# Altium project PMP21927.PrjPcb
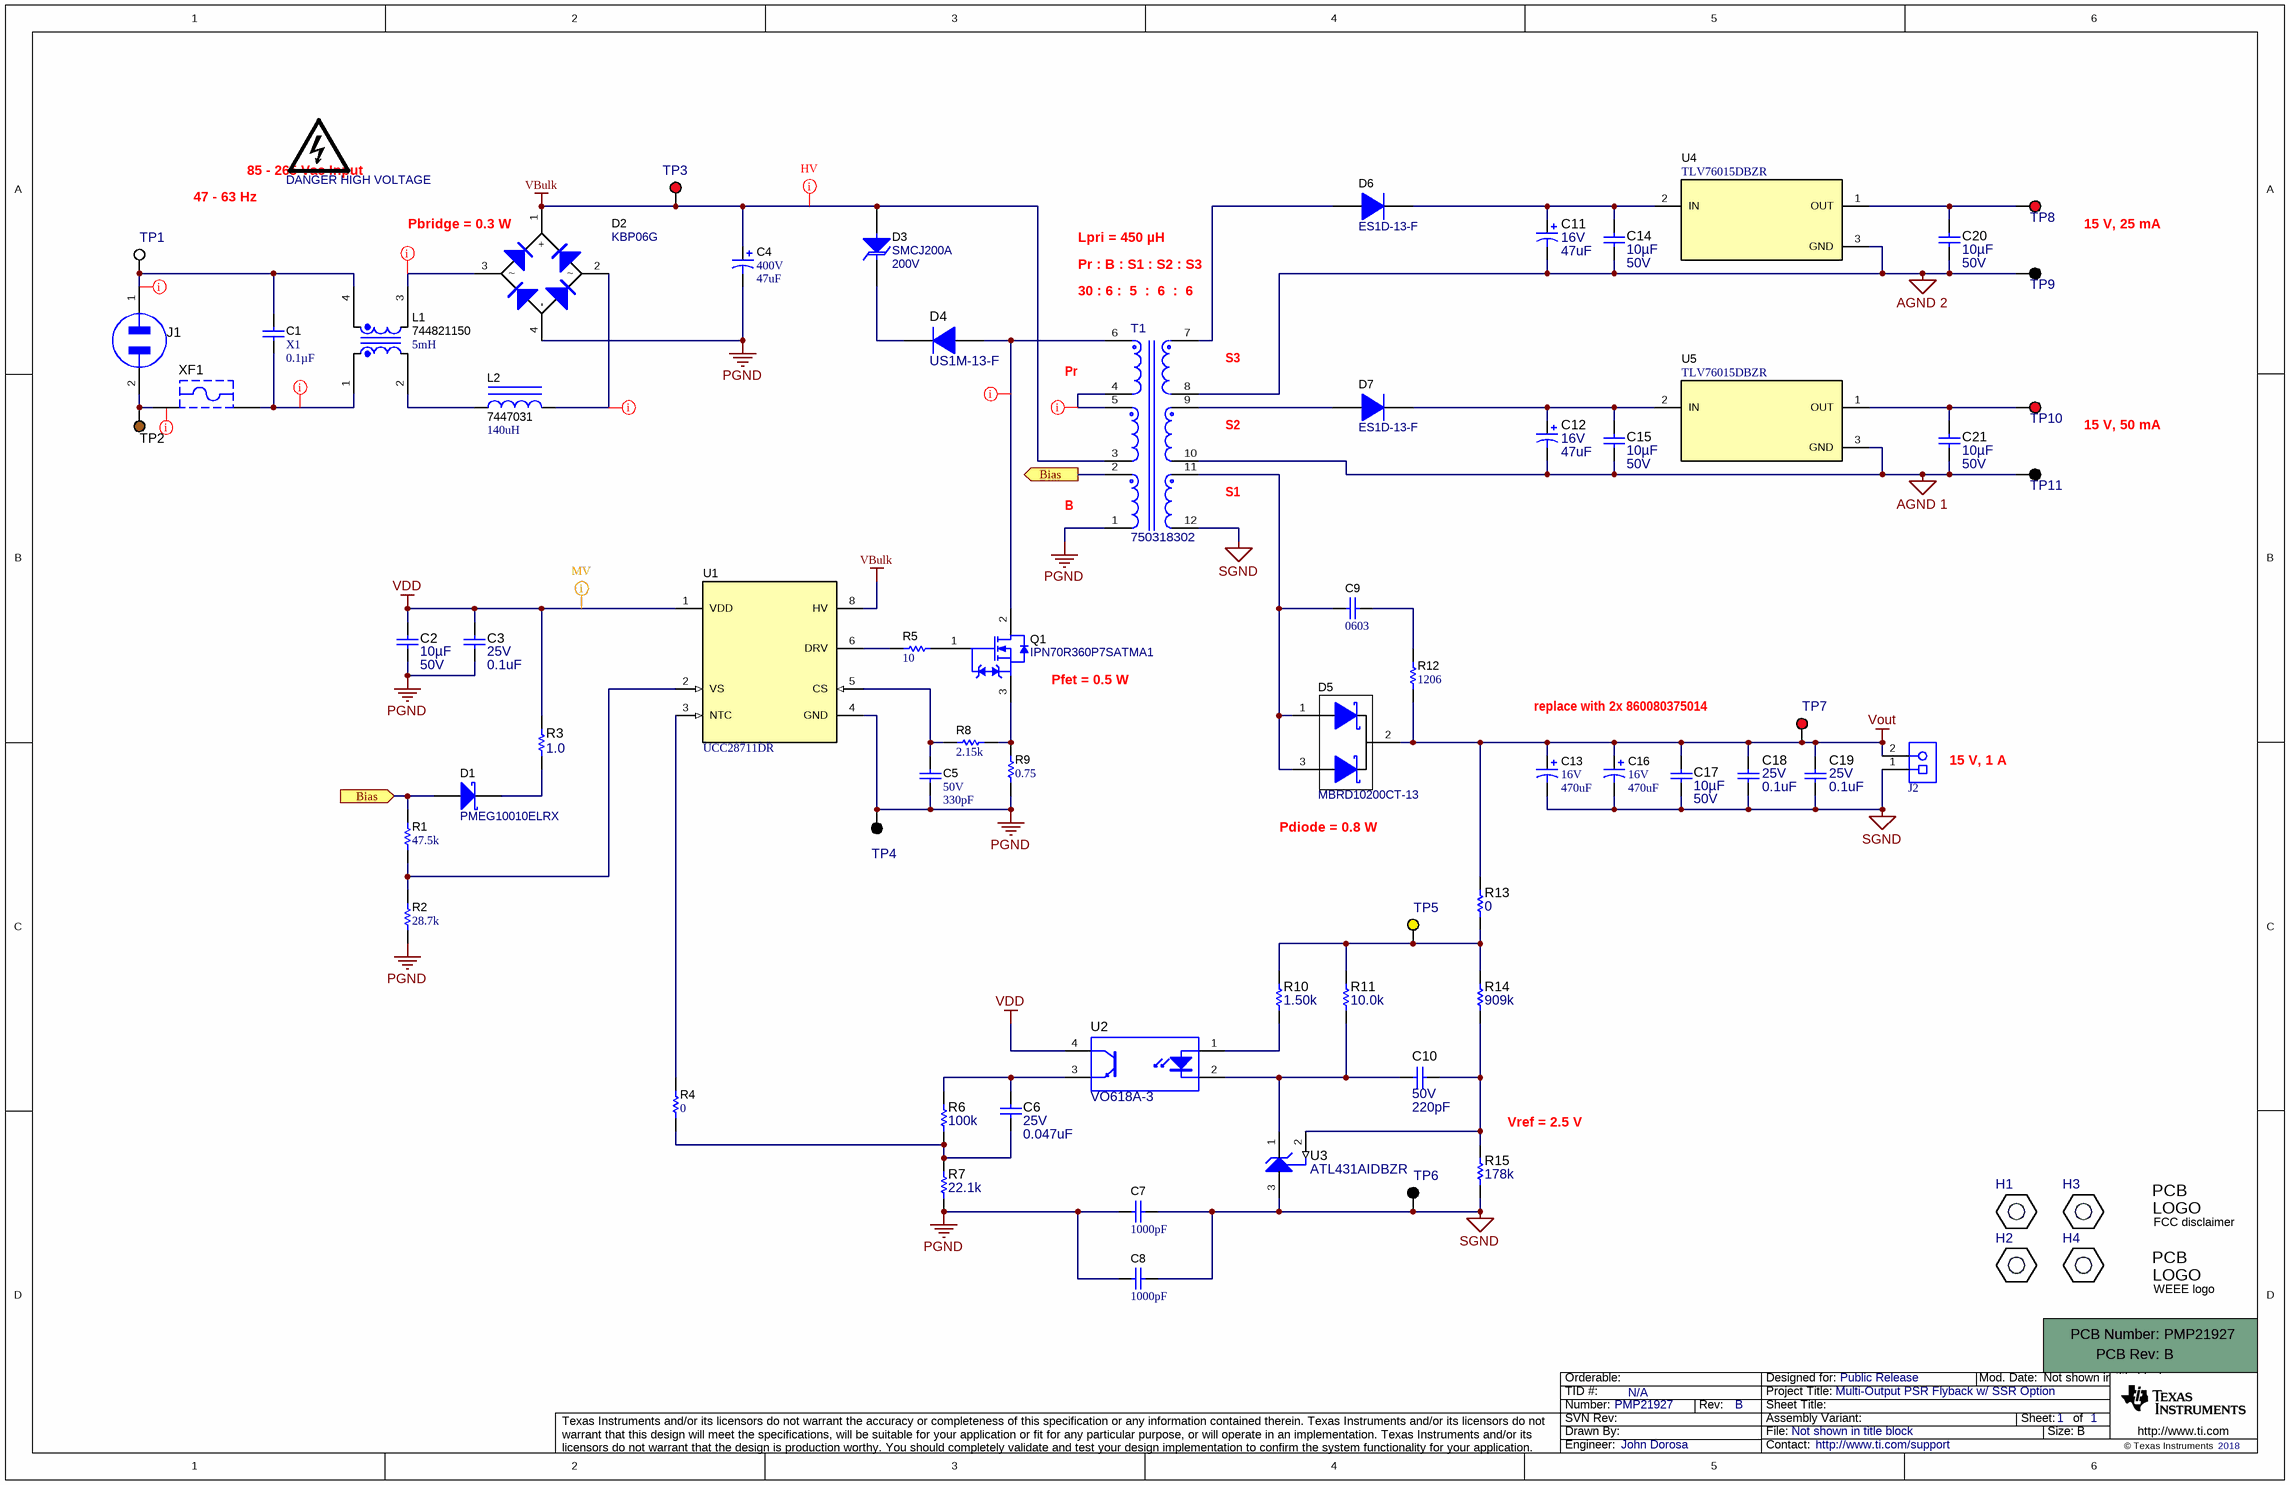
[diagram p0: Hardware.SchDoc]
CopyrightYear: 2018; PCB_Layout: John Dorosa; PCB_Rev: B; PRJ_Customer: Public Release; PRJ_Engineer: John Dorosa; PRJ_Number: PMP21927; PRJ_Title: Multi-Output PSR Flyback w/ SSR Option; SCH_Rev: B; TechSupport: http://www.ti.com/support; TID: N/A
1 sheet, 74 parts. Net scope: flat (ports and power ports of the same name join across sheets).
Board file: PCB.PcbDoc

## Sheet Hardware.SchDoc
size 431 x 279 mm; Date: Not shown in title block; ApprovedBy: Not shown in title block; CheckedBy: Not shown in title block; Author: Not shown in title block; CompanyName: Not shown in title block; Engineer: Not shown in title block; Organization: Not shown in title block; Address1: Not shown in title block; Address2: Not shown in title block; Address3: Not shown in title block; Address4: Not shown in title block; DocumentNumber: 1; Revision: Use project parameter SCH_Rev; SheetNumber: 1; SheetTotal: 1; PageSetup: Record=PageOptions¦CenterHorizontal=True¦CenterVertical=True¦PrintScale=1.00¦XCorrection=1.00¦YCorrection=1.00¦PrintKind=0¦BorderSize=5000000¦LeftOffset=0¦BottomOffset=0¦Orientation=2¦PaperLength=1000¦PaperWidth=1000¦Scale=100¦PaperSource=15¦PrintQuality=600¦MediaType=1¦DitherType=10¦PaperKind=Letter¦PrintScaleMode=1

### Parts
!PCB1  Printed Circuit Board  (value not drawn)  (mechanical)
C1  AC_Safety: X1  ValueDisplayed: 0.1µF  [Kemet_1800x1100x1900]  (hidden comment: R474I310050A1K)
C2  ValueDisplayed: 10µF  VDC_V: 50V  [1206_190]  (hidden comment: CGA5L1X7R1H106K160AC)
C3  VDC_V: 25V  ValueDisplayed: 0.1uF  [0603]  (hidden comment: C1608X7R1E104K080AA)
C4  VDC_V: 400V  ValueDisplayed: 47uF  [CAPPR7_5-16X25_HorizontalDown]  (hidden comment: UCS2G470MHD)
C5  VDC_V: 50V  ValueDisplayed: 330pF  [0402]  (hidden comment: GRM155R71H331KA01D)
C6  VDC_V: 25V  ValueDisplayed: 0.047uF  [0603]  (hidden comment: GRM188R71E473KA01D)
C7  ValueDisplayed: 1000pF  [VY1_900x500x1300]  (hidden comment: VY1102M35Y5UQ63V0)
C8  ValueDisplayed: 1000pF  [VY1_900x500x1300]  (hidden comment: VY1102M35Y5UQ63V0)
C9  GRM188R72A102KA01D  [0603]  (value not drawn)
C10  VDC_V: 50V  ValueDisplayed: 220pF  [0603]  (hidden comment: GRM188R71H221KA01D)
C11  VDC_V: 16V  ValueDisplayed: 47uF  [FC_500x1100]  (hidden comment: EEUFC1C470)
C12  VDC_V: 16V  ValueDisplayed: 47uF  [FC_500x1100]  (hidden comment: EEUFC1C470)
C13  VDC_V: 16V  ValueDisplayed: 470uF  [Chemi-Con_1000x1250]  (hidden comment: EKZE160ELL471MJC5S)
C14  ValueDisplayed: 10µF  VDC_V: 50V  [1206_190]  (hidden comment: CGA5L1X7R1H106K160AC)
C15  ValueDisplayed: 10µF  VDC_V: 50V  [1206_190]  (hidden comment: CGA5L1X7R1H106K160AC)
C16  VDC_V: 16V  ValueDisplayed: 470uF  [Chemi-Con_1000x1250]  (hidden comment: EKZE160ELL471MJC5S)
C17  ValueDisplayed: 10µF  VDC_V: 50V  [1206_190]  (hidden comment: CGA5L1X7R1H106K160AC)
C18  VDC_V: 25V  ValueDisplayed: 0.1uF  [0603]  (hidden comment: C1608X7R1E104K080AA)
C19  VDC_V: 25V  ValueDisplayed: 0.1uF  [0603]  (hidden comment: C1608X7R1E104K080AA)
C20  ValueDisplayed: 10µF  VDC_V: 50V  [1206_190]  (hidden comment: CGA5L1X7R1H106K160AC)
C21  ValueDisplayed: 10µF  VDC_V: 50V  [1206_190]  (hidden comment: CGA5L1X7R1H106K160AC)
D1  PMEG10010ELRX  [SOD-123W]
D2  KBP06G  [KBP]
D3  SMCJ200A  value 200V  [SMC]
D4  US1M-13-F  [SMA]
D5  MBRD10200CT-13  [DPAK]
D6  ES1D-13-F  [SMA]
D7  ES1D-13-F  [SMA]
H1  4826  [KEYSTONE_4826]  (value not drawn)
H2  4826  [KEYSTONE_4826]  (value not drawn)
H3  4826  [KEYSTONE_4826]  (value not drawn)
H4  4826  [KEYSTONE_4826]  (value not drawn)
J1  770W-X2/10  [CONN_AC_770W-SERIES]  (value not drawn)
J2  691214310002  [Wurth_691214310002]  (value not drawn)
L1  744821150  value 5mH  [WE-CMB_XS]
L2  7447031  ValueDisplayed: 140uH  [WE-FI_1350x700]
LOGO1  DANGER HIGH VOLTAGE  [IEC_HighVoltage_Medium]  (no BOM)
Logo2  FCC disclaimer  [FCC_disclaimer]  (no BOM)
Logo3  WEEE logo  [WEEE_Minimum]  (no BOM)
Q1  IPN70R360P7SATMA1  [PG-SOT223]
R1  ValueDisplayed: 47.5k  [0603]  (hidden comment: CRCW060347K5FKEA)
R2  ValueDisplayed: 28.7k  [0603]  (hidden comment: CRCW060328K7FKEA)
R3  ValueDisplayed: 1.0  [0603]  (hidden comment: CRCW06031R00JNEA)
R4  ValueDisplayed: 0  [1206]  (hidden comment: CRCW12060000Z0EA)
R5  ValueDisplayed: 10  [0603]  (hidden comment: CRCW060310R0JNEA)
R6  ValueDisplayed: 100k  [0603]  (hidden comment: CRCW0603100KFKEA)
R7  ValueDisplayed: 22.1k  [0603]  (hidden comment: CRCW060322K1FKEA)
R8  ValueDisplayed: 2.15k  [0603]  (hidden comment: CRCW06032K15FKEA)
R9  ValueDisplayed: 0.75  [2010]  (hidden comment: CSRN2010FKR750)
R10  ValueDisplayed: 1.50k  [0603]  (hidden comment: CRCW06031K50FKEA)
R11  ValueDisplayed: 10.0k  [0603]  (hidden comment: CRCW060310K0FKEA)
R12  CRCW1206200RJNEA  [1206]  (value not drawn)
R13  ValueDisplayed: 0  [0603]  (hidden comment: CRCW06030000Z0EA)
R14  ValueDisplayed: 909k  [0603]  (hidden comment: CRCW0603909KFKEA)
R15  ValueDisplayed: 178k  [0603]  (hidden comment: CRCW0603178KFKEA)
T1  750318302  [FP-750318302_TRANS_PTH_33MM0_26MM3-MFG]
TP1  5012  [Keystone5012]  (value not drawn)
TP2  5125  [Keystone5125]  (value not drawn)
TP3  5010  [Keystone5010]  (value not drawn)
TP4  5011  [Keystone5011]  (value not drawn)
TP5  5014  [Keystone5014]  (value not drawn)
TP6  5011  [Keystone5011]  (value not drawn)
TP7  5010  [Keystone5010]  (value not drawn)
TP8  5010  [Keystone5010]  (value not drawn)
TP9  5011  [Keystone5011]  (value not drawn)
TP10  5010  [Keystone5010]  (value not drawn)
TP11  5011  [Keystone5011]  (value not drawn)
U1  UCC28711DR  [D0007A_N]
U2  VO618A-3  [DIP-4]
U3  ATL431AIDBZR  [DBZ0003A_N]
U4  TLV76015DBZR  [DBZ0003A_N]
U5  TLV76015DBZR  [DBZ0003A_N]
XF1  56000001009  [FuseHolder_560000010]  (value not drawn)

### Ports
Bias (in), Bias (out)

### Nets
AGND 1: C12.2(-) C15.2 C21.2 T1.10 TP11.1 U5.3(GND)
AGND 2: C11.2(-) C14.2 C20.2 T1.8 TP9.1 U4.3(GND)
PGND: C2.2 C3.1 C4.2(-) C5.2 C7.2 C8.2 D2.4(-) R2.1 R7.1 R9.1 T1.1 TP4.1 U1.4(GND)
SGND: C7.1 C8.1 C13.2(-) C16.2(-) C17.2 C18.1 C19.1 J2.1 R15.1 T1.12 TP6.1 U3.3(ANODE)
VBulk: C4.1(+) D2.1(+) D3.2(A) T1.3 TP3.1 U1.8(HV)
VDD: C2.1 C3.2 R3.2 U1.1(VDD) U2.4(C)
Vout: C13.1(+) C16.1(+) C17.1 C18.2 C19.2 D5.2(K) J2.2 R12.1 R13.2 TP7.1
Bias: D1.2(A) R1.2 T1.2 ; port Bias
NetC1_1: C1.1 L1.1 XF1.1
NetC1_2: C1.2 J1.1(Neutral) L1.4 TP1.1
NetC5_1: C5.1 R8.1 U1.5(CS)
NetC6_1: C6.1 R6.2 U2.3(E)
NetC6_2: C6.2 R4.1 R6.1 R7.2
NetC9_1: C9.1 R12.2
NetC9_2: C9.2 D5.1(A) D5.3(A) T1.11
NetC10_1: C10.1 R14.1 R15.2 U3.2(REF)
NetC10_2: C10.2 R11.1 U2.2(K) U3.1(CATHODE)
NetC11_1: C11.1(+) C14.1 D6.1(K) U4.2(IN)
NetC12_1: C12.1(+) C15.1 D7.1(K) U5.2(IN)
NetC20_1: C20.1 TP8.1 U4.1(OUT)
NetC21_1: C21.1 TP10.1 U5.1(OUT)
NetD1_1: D1.1(K) R3.1
NetD2_2: D2.2 L2.2
NetD2_3: D2.3 L1.3
NetD3_1: D3.1(K) D4.1(K)
NetD4_2: D4.2(A) Q1.2(D) T1.6
NetD6_2: D6.2(A) T1.7
NetD7_2: D7.2(A) T1.9
NetJ1_2: J1.2(Hot) TP2.1 XF1.2
NetL1_2: L1.2 L2.1
NetQ1_1: Q1.1(G) R5.2
NetQ1_3: Q1.3(S) R8.2 R9.2
NetR1_1: R1.1 R2.2 U1.2(VS)
NetR4_2: R4.2 U1.3(NTC)
NetR5_1: R5.1 U1.6(DRV)
NetR10_1: R10.1 U2.1(A)
NetR10_2: R10.2 R11.2 R13.1 R14.2 TP5.1
NetT1_4: T1.4 T1.5

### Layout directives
mark named HV: (no net found under the mark), NetC1_1, NetC1_2, NetD2_2, NetD2_3, NetD4_2, NetT1_4, VBulk
mark named MV: VDD

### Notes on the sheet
- 47 - 63 Hz
- 85 - 265 Vac Input
- (near D2) Pbridge = 0.3 W
- 15 V, 25 mA
- Lpri = 450 µH
- Pr : B : S1 : S2 : S3
- (near T1) 30 : 6 :  5  :  6  :  6
- S3
- Pr
- S2
- 15 V, 50 mA
- S1
- B
- (near Q1) Pfet = 0.5 W
- replace with 2x 860080375014
- (near J2) 15 V, 1 A
- (near D5) Pdiode = 0.8 W
- (near R15) Vref = 2.5 V

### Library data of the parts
!PCB1 = CMP-0003618-2: Manufacturer: Any; PartNumber: PMP21927
C1 = CMP-0074799-2: CAP, Film, 0.1 µF, X1 440 VAC, +/- 10%, AEC-Q200 Grade 1, TH; Manufacturer: Kemet; TaMin_C: -40°C; Polarized: N; SizeAreaWB_mm2: 260.0; Value: 0.1uF; TaMax_C: 110°C; VAC_X: 440; SizeZ_mm: 19.1; SizeX_mm: 18.0; SizeY_mm: 11.0; Cap_Case: 18x11x19mm; Value2: 1000V; SizeArea_mm2: 198.0; AEC Qualified: Y; Cap_F: 100nF; VDC_V: 1kV; AEC Grade: 1; AEC Category: Q200
C2 C14 C15 C17 C20 C21 = CMP-0085950-1: CAP, CERM, 10 µF, 50 V,+/- 10%, X7R, AEC-Q200 Grade 1, 1206; Manufacturer: TDK; SizeZ_mm: 1.9; Value: 10uF; Cap_Case: 1206; AEC Grade: 1; TaMin_C: -55°C; U/M: EA; SizeArea_mm2: 5.12; TaMax_C: 125°C; AEC Qualified: Y; AEC Category: Q200; SizeX_mm: 3.2; SizeY_mm: 1.6; Polarized: N; SizeAreaWB_mm2: 10.92
C3 C18 C19 = CMP-0007039-5: CAP, CERM, 0.1 uF, 25 V, +/- 10%, X7R, 0603; Manufacturer: TDK; TaMin_C: -55°C; Polarized: N; SizeAreaWB_mm2: 4.68; Value1: Unknown; U/M: EA; Value: 0.1uF; TaMax_C: 125°C; SizeZ_mm: 1; SizeX_mm: 1.6; SizeY_mm: 0.8; SizeArea_mm2: 1.28; Cap_F: 100nF; AEC Category: Q200
C4 = CMP-0010241-1: CAP, AL, 47 uF, 400 V, +/- 20%, TH; Manufacturer: Nichicon; TaMin_C: -40°C; Polarized: Y; SizeAreaWB_mm2: 324; Value1: Unknown; U/M: EA; Value: 47uF; TaMax_C: 105°C; SizeZ_mm: 25; SizeX_mm: 16; Cap_Case: Radial  16x25mm; SizeArea_mm2: 256; CompType: Capacitor; AEC Qualified: N; Cap_F: 47µF; IRMS_A: 1.18A; AEC Category: Q200
C5 = CMP-0006687-2: CAP, CERM, 330 pF, 50 V, +/- 10%, X7R, 0402; Manufacturer: MuRata; TaMin_C: -55°C; Polarized: N; SizeAreaWB_mm2: 3; Value1: Unknown; U/M: EA; Value: 330pF; TaMax_C: 125°C; SizeZ_mm: 0.6; SizeX_mm: 1; SizeY_mm: 0.5; AEC Category: Q200
C6 = CMP-0007423-4: CAP, CERM, 0.047 uF, 25 V, +/- 10%, X7R, 0603; Manufacturer: MuRata; TaMin_C: -55°C; Polarized: N; SizeAreaWB_mm2: 4.68; Value1: Unknown; U/M: EA; TaMax_C: 125°C; SizeZ_mm: 1; SizeX_mm: 1.6; SizeY_mm: 0.8; SizeArea_mm2: 1.28; Cap_F: 47nF; AEC Category: Q200
C7 C8 = CMP-0086097-1: CAP, CERM, 1000 pF, X1 760 VAC/Y1 500 VAC, +/- 20%, Y5U, 9x5mm; Manufacturer: Vishay-Bccomponents; Cap_F: 1nF; TaMin_C: -40°C; Polarized: N; VAC_Y: 500V; AEC Category: Q200; SizeY_mm: 5; SizeZ_mm: 13; U/M: EA; SizeArea_mm2: 53; VAC_X: 760V; SizeX_mm: 10.6; TaMax_C: 125°C; AC_Safety: X1Y1; SizeAreaWB_mm2: 88.2; Value: 1000pF
C9 = CMP-0007467-4: CAP, CERM, 1000 pF, 100 V, +/- 10%, X7R, 0603; Manufacturer: MuRata; TaMin_C: -55°C; Polarized: N; SizeAreaWB_mm2: 4.68; Value1: Unknown; U/M: EA; Value: 1000pF; TaMax_C: 125°C; SizeZ_mm: 1; SizeX_mm: 1.6; SizeY_mm: 0.8; Value2: 100V; SizeArea_mm2: 1.28; Cap_F: 1nF; AEC Category: Q200
C10 = CMP-0007442-5: CAP, CERM, 220 pF, 50 V, +/- 10%, X7R, 0603; Manufacturer: MuRata; TaMin_C: -55°C; Polarized: N; SizeAreaWB_mm2: 4.68; Value1: Unknown; U/M: EA; Value: 220pF; TaMax_C: 125°C; SizeZ_mm: 1; SizeX_mm: 1.6; SizeY_mm: 0.8; SizeArea_mm2: 1.28; AEC Category: Q200
C11 C12 = CMP-0010335-1: CAP, AL, 47 uF, 16 V, +/- 20%, 0.8 ohm, AEC-Q200 Grade 2, TH; Manufacturer: Panasonic; TaMin_C: -55°C; ESR_ohm: 0.8; Polarized: Y; SizeAreaWB_mm2: 49; Value1: 0.8 ohm; U/M: EA; Value: 47uF; TaMax_C: 105°C; SizeZ_mm: 12; SizeX_mm: 5; Cap_Case: 5x11mm; SizeArea_mm2: 25; CompType: Capacitor; Cap_F: 47µF; IRMS_A: 175mA; AEC Grade: 2; AEC Category: Q200
C13 C16 = CMP-0010396-1: CAP, AL, 470 uF, 16 V, +/- 20%, TH; Manufacturer: Chemi-Con; TaMin_C: -40°C; Polarized: Y; SizeAreaWB_mm2: 144; Value1: Unknown; U/M: EA; Value: 470uF; TaMax_C: 105°C; SizeZ_mm: 14; SizeX_mm: 10; Cap_Case: 10x12.5; SizeArea_mm2: 100; CompType: Capacitor; AEC Qualified: N; Cap_F: 470µF; IRMS_A: 1.03A; AEC Category: Q200
D1 = CMP-0028782-2: Diode, Schottky, 100 V, 1 A, AEC-Q101, SOD-123W; Manufacturer: Nexperia; Green_REACh: Incomplete; SizeX_mm: 3.5; SizeAreaWB_mm2: 12.15; SizeY_mm: 1.7; AEC Category: Q101; Value: 100V; SizeZ_mm: 1; AEC Qualified: Y; TJmax_C: 175°C; SizeArea_mm2: 5.95; Vf_V: 770mV; Io_A: 1A; Value2: 0.77V; Green_Lifecycle: Not Set
D2 = CMP-0029224-3: Diode, Switching-Bridge, 600 V, 1.5 A, TH; Manufacturer: Diodes Inc.; Value2: 1.1V; AEC Category: Q101; SizeAreaWB_mm2: 79.75; Value: 600V; Io_A: 1.5A; RJC_CperW: 18; SizeY_mm: 3.5; Green_Lifecycle: Not Set; SizeX_mm: 12.5; SizeZ_mm: 12.69; TJmax_C: 150°C; SizeArea_mm2: 43.75; Green_REACh: Incomplete
D3 = CMP-0065113-3: Diode, TVS, Uni, 200 V, 324 Vc, SMC; Manufacturer: Littelfuse; AEC Qualified: N; RJA_CperW: 75; Value1: 1500W; Ppk: 1.5kW; Vc: 324V; SizeAreaWB_mm2: 83.2686; SizeX_mm: 8.13; Ipp: 4.6A; AEC Category: Q101; SizeY_mm: 6.22; SizeZ_mm: 2.6; SizeArea_mm2: 50.5686; Vbr_Min: 224V; Vbr_Max: 247V
D4 = CMP-0076882-2: Diode, Ultrafast, 1000 V, 1 A, SMA; Manufacturer: Diodes Inc.; AEC Category: Q101; Value2: 1.7V; SizeZ_mm: 2.87; Green_REACh: Incomplete; Value: 1000V; Value1: 1A; SizeAreaWB_mm2: 37.3428; Green_Lifecycle: Not Set; RJC_CperW: 30.0; SizeX_mm: 5.59; SizeArea_mm2: 16.3228; Vr_V: 1kV; TJmax_C: 150°C; SizeY_mm: 2.92
D5 = CMP-0077020-3: Diode, Schottky, 200 V, 5 A, DPAK; Manufacturer: Diodes Inc.; Vf_V: 910mV; TJmax_C: 175°C; RJC_CperW: 6.0; Green_Lifecycle: Not Set; SizeAreaWB_mm2: 101.7114; Value1: 5A; SizeX_mm: 9.91; Green_REACh: Incomplete; SizeZ_mm: 2.29; Value: 200V; SizeArea_mm2: 64.8114; AEC Category: Q101; SizeY_mm: 6.54; Value2: 0.91V
D6 D7 = CMP-0029024-2: Diode, Ultrafast, 200 V, 1 A, SMA; Manufacturer: Diodes Inc.; Value2: 0.92V; Green_Lifecycle: Active; Io_A: 1A; Vf_V: 920mV; Value: 200V; SizeX_mm: 5.59; AEC Category: Q101; TJmax_C: 150°C; SizeAreaWB_mm2: 37.3428; SizeArea_mm2: 16.3228; RJC_CperW: 25; SizeZ_mm: 2.87; Green_REACh: Passed; SizeY_mm: 2.92
H1-H4 = CMP-0003686-1: Manufacturer: Keystone; CompType: Standoff
J1 = CMP-0074930-1: AC Receptacle, 2.5A, R/A, TH; Manufacturer: Qualtek Electronics Corporation; CNHeader: False; Green_Lifecycle: Not Set; Green_REACh: Incomplete
J2 = CMP-0054822-2: Terminal Block, 2x1, 3.81mm, 24-16 AWG, 10A, 300VAC, TH; Manufacturer: Wurth Elektronik; CT: TRUE; CNHeader: FALSE; Green_Lifecycle: Active; Green_REACh: Passed
L1 = CMP-0084275-1: Coupled inductor, 5 mH, 0.22 ohm, TH; Manufacturer: Wurth Elektronik; SizeY_mm: 7.5; DCR_ohm: 0.22; SizeZ_mm: 20.5; AEC Category: Q200; SizeAreaWB_mm2: 161.5; SizeX_mm: 15; SizeArea_mm2: 112.5; AEC Qualified: N
L2 = CMP-0064732-2: Inductor, Toroid, Powdered Iron, 140 uH, 1 A, 0.11 ohm, TH; Manufacturer: Wurth Elektronik; Irms: 1A @ 40C rise; Green_Lifecycle: Active; SizeAreaWB_mm2: 139.5; DCR_ohm: 0.11; Green_REACh: Passed; Value: 140uH; Imax_A: 1A; SizeZ_mm: 13.5; SizeX_mm: 7; SizeArea_mm2: 94.5; Ind_H: 140µH; AEC Qualified: N; AEC Category: Q200
LOGO1 = CMP-0074835-1: IEC 61010-1 High Voltage Warning; SymbolCreator: a0412235
Logo2 = CMP-0074847-1: FCC_disclaimer; Library Reference: Logo
Logo3 = CMP-0074769-1
Q1 = CMP-0750130-1: MOSFET, N-CH, 700 V, 12.5 A, PG-SOT223; Alternate Manufacturer: None; Manufacturer: Infineon Technologies; Value2: 16.4 nC; Value: 700V; ChType: N; SizeY_mm: 6.5; SizeZ_mm: 1.8; IdsMax_A: 12.5A; Vgs_V: 16V; QgTyp_nC: 16.4; AEC Category: Q101; SizeAreaWB_mm2: 76.5; SizeX_mm: 7; SizeArea_mm2: 45.5; Value1: ? ohm; ChMode: Enhancement
R1 = CMP-0022439-4: RES, 47.5 k, 1%, 0.1 W, AEC-Q200 Grade 0, 0603; Manufacturer: Vishay-Dale; Power_W: 100mW; TempCo: 100 ppm/C; Value_Code: 47k5; Value: 47.5k; EIA_Code: E96; SizeX_mm: 1.6; SizeY_mm: 0.8; SizeZ_mm: 1; Value2: 0.1W; SizeArea_mm2: 1.28; AEC Qualified: Y; VDC_V: 75V; AEC Category: Q200; AEC Grade: 0
R2 = CMP-0022261-4: RES, 28.7 k, 1%, 0.1 W, AEC-Q200 Grade 0, 0603; Manufacturer: Vishay-Dale; Power_W: 100mW; TempCo: 100 ppm/C; Value_Code: 28k7; Value: 28.7k; EIA_Code: E96; SizeX_mm: 1.6; SizeY_mm: 0.8; SizeZ_mm: 1; Value2: 0.1W; SizeArea_mm2: 1.28; AEC Qualified: Y; VDC_V: 75V; AEC Category: Q200; AEC Grade: 0
R3 = CMP-0025743-4: RES, 1.0, 5%, 0.1 W, AEC-Q200 Grade 0, 0603; Manufacturer: Vishay-Dale; Power_W: 100mW; TempCo: 200 ppm/C; Value_Code: 1R00; Value: 1.0; EIA_Code: E24; Res_ohm: 1; SizeX_mm: 1.6; SizeY_mm: 0.8; Value2: 0.1W; SizeArea_mm2: 1.28; AEC Qualified: Y; VDC_V: 75V; AEC Category: Q200; AEC Grade: 0
R4 = CMP-0018573-3: RES, 0, 5%, 0.25 W, AEC-Q200 Grade 0, 1206; Manufacturer: Vishay-Dale; Power_W: 250mW; TempCo: 200 ppm/C; Value_Code: 0000; Value: 0; EIA_Code: E24; SizeX_mm: 3.2; SizeY_mm: 1.6; SizeZ_mm: 1.35; Value2: 0.25W; SizeArea_mm2: 5.12; AEC Qualified: Y; VDC_V: 200V; AEC Category: Q200
R5 = CMP-0025703-4: RES, 10, 5%, 0.1 W, AEC-Q200 Grade 0, 0603; Manufacturer: Vishay-Dale; Power_W: 100mW; TempCo: 200 ppm/C; Value_Code: 10R0; Value: 10; EIA_Code: E24; SizeX_mm: 1.6; SizeY_mm: 0.8; SizeZ_mm: 1; Value2: 0.1W; SizeArea_mm2: 1.28; AEC Qualified: Y; VDC_V: 75V; AEC Category: Q200; AEC Grade: 0
R6 = CMP-0021990-4: RES, 100 k, 1%, 0.1 W, AEC-Q200 Grade 0, 0603; Manufacturer: Vishay-Dale; Power_W: 100mW; TempCo: 100 ppm/C; Value: 100k; EIA_Code: E96; SizeX_mm: 1.6; SizeY_mm: 0.8; SizeZ_mm: 1; Value2: 0.1W; SizeArea_mm2: 1.28; AEC Qualified: Y; VDC_V: 75V; AEC Category: Q200; AEC Grade: 0
R7 = CMP-0022220-4: RES, 22.1 k, 1%, 0.1 W, AEC-Q200 Grade 0, 0603; Manufacturer: Vishay-Dale; Power_W: 100mW; TempCo: 100 ppm/C; Value_Code: 22k1; Value: 22.1k; EIA_Code: E96; SizeX_mm: 1.6; SizeY_mm: 0.8; SizeZ_mm: 1; Value2: 0.1W; SizeArea_mm2: 1.28; AEC Qualified: Y; VDC_V: 75V; AEC Category: Q200; AEC Grade: 0
R8 = CMP-0022271-4: RES, 2.15 k, 1%, 0.1 W, AEC-Q200 Grade 0, 0603; Manufacturer: Vishay-Dale; Power_W: 100mW; TempCo: 100 ppm/C; Value_Code: 2k15; Value: 2.15k; EIA_Code: E96; SizeX_mm: 1.6; SizeY_mm: 0.8; SizeZ_mm: 1; Value2: 0.1W; SizeArea_mm2: 1.28; AEC Qualified: Y; VDC_V: 75V; AEC Category: Q200; AEC Grade: 0
R9 = CMP-0016531-2: RES, 0.75, 1%, 1 W, 2010; Manufacturer: Stackpole Electronics Inc; Power_W: 1W; TempCo: 250 ppm/C; Value_Code: R750; U/M: EA; Value: 0.75; EIA_Code: E96; SizeX_mm: 5; SizeY_mm: 2.5; SizeZ_mm: 1.66; SizeArea_mm2: 12.5; AEC Category: Q200
R10 = CMP-0022126-4: RES, 1.50 k, 1%, 0.1 W, AEC-Q200 Grade 0, 0603; Manufacturer: Vishay-Dale; Power_W: 100mW; TempCo: 100 ppm/C; Value_Code: 1k50; Value: 1.50k; EIA_Code: E96; Res_ohm: 1.5k; SizeX_mm: 1.6; SizeY_mm: 0.8; SizeZ_mm: 1; Value2: 0.1W; SizeArea_mm2: 1.28; AEC Qualified: Y; VDC_V: 75V; AEC Category: Q200; AEC Grade: 0
R11 = CMP-0021998-4: RES, 10.0 k, 1%, 0.1 W, AEC-Q200 Grade 0, 0603; Manufacturer: Vishay-Dale; Power_W: 100mW; TempCo: 100 ppm/C; Value_Code: 10k0; Value: 10.0k; EIA_Code: E96; Res_ohm: 10k; SizeX_mm: 1.6; SizeY_mm: 0.8; SizeZ_mm: 1; Value2: 0.1W; SizeArea_mm2: 1.28; AEC Qualified: Y; VDC_V: 75V; AEC Category: Q200; AEC Grade: 0
R12 = CMP-0018625-3: RES, 200, 5%, 0.25 W, AEC-Q200 Grade 0, 1206; Manufacturer: Vishay-Dale; Power_W: 250mW; TempCo: 200 ppm/C; Value_Code: 200R; Value: 200; EIA_Code: E24; SizeX_mm: 3.2; SizeY_mm: 1.6; SizeZ_mm: 1.35; Value2: 0.25W; SizeArea_mm2: 5.12; AEC Qualified: Y; VDC_V: 200V; AEC Category: Q200; AEC Grade: 0
R13 = CMP-0025697-4: RES, 0, 5%, 0.1 W, AEC-Q200 Grade 0, 0603; Manufacturer: Vishay-Dale; Power_W: 100mW; TempCo: 200 ppm/C; Value_Code: 0000; Value: 0; EIA_Code: E24; SizeX_mm: 1.6; SizeY_mm: 0.8; SizeZ_mm: 1; Value2: 0.1W; SizeArea_mm2: 1.28; AEC Qualified: Y; VDC_V: 75V; AEC Category: Q200
R14 = CMP-0022649-3: RES, 909 k, 1%, 0.1 W, AEC-Q200 Grade 0, 0603; Manufacturer: Vishay-Dale; Power_W: 100mW; TempCo: 100 ppm/C; Value: 909k; EIA_Code: E96; SizeX_mm: 1.6; SizeY_mm: 0.8; SizeZ_mm: 1; Value2: 0.1W; SizeArea_mm2: 1.28; AEC Qualified: Y; VDC_V: 75V; AEC Category: Q200; AEC Grade: 0
R15 = CMP-0022087-4: RES, 178 k, 1%, 0.1 W, AEC-Q200 Grade 0, 0603; Manufacturer: Vishay-Dale; Power_W: 100mW; TempCo: 100 ppm/C; Value: 178k; EIA_Code: E96; SizeX_mm: 1.6; SizeY_mm: 0.8; SizeZ_mm: 1; Value2: 0.1W; SizeArea_mm2: 1.28; AEC Qualified: Y; VDC_V: 75V; AEC Category: Q200; AEC Grade: 0
T1 = CMP-0087102-1: TRANSFORMER; Manufacturer: Wurth Electronics; DCR_ohm: 0.52; AEC Qualified: No; Ind_H: 450µH; Ns1toNp: 6:1; SizeZ_mm: 14mm; Rsec1_ohm: 0.755
TP1 = CMP-0055149-1: Test Point, Multipurpose, White, TH; Manufacturer: Keystone; CNHeader: FALSE; Green_Lifecycle: Active; Green_REACh: Passed; ContactFinish: Silver; CT: TRUE
TP2 = CMP-0055157-1: Test Point, Multipurpose, Brown, TH; Manufacturer: Keystone; CNHeader: FALSE; Green_Lifecycle: Active; Green_REACh: Passed; ContactFinish: Silver; CT: TRUE
TP3 TP7 TP8 TP10 = CMP-0055147-1: Test Point, Multipurpose, Red, TH; Manufacturer: Keystone; CNHeader: FALSE; Green_Lifecycle: Active; Green_REACh: Passed; ContactFinish: Silver; CT: TRUE
TP4 TP6 TP9 TP11 = CMP-0055148-1: Test Point, Multipurpose, Black, TH; Manufacturer: Keystone; CNHeader: FALSE; Green_Lifecycle: Active; Green_REACh: Passed; ContactFinish: Silver; CT: TRUE
TP5 = CMP-0055151-1: Test Point, Multipurpose, Yellow, TH; Manufacturer: Keystone; CNHeader: FALSE; Green_Lifecycle: Active; Green_REACh: Passed; ContactFinish: Silver; CT: TRUE
U1 = CMP-0067231-2: Constant-Voltage, Constant-Current PWM Controller with Primary-Side Regulation, D0007A (SOIC-7); Alternate Manufacturer: Texas Instruments; SizeAreaWB_mm2: 55.2; U/M: EA; SizeZ_mm: 1.75; SizeX_mm: 6.0; SizeY_mm: 4.9; SizeArea_mm2: 29.4; CompType: IC; AEC Category: Q200; AEC Qualified: N
U2 = CMP-0083653-1: Optocoupler, 5.3 kV, 100-200% CTR, SMT; Manufacturer: Vishay-Semiconductor; CTR (Max): 200%; SizeAreaWB_mm2: 71.064; CTR (Min): 100%; SizeZ_mm: 5; SizeX_mm: 8.8; SizeY_mm: 4.58; SizeArea_mm2: 40.304; Voltage_Isolation_Vrms: 5.3kV
U3 = CMP-0066199-1: 2.5V Low Iq Adjustable Precision Shunt Regulator, DBZ0003A (SOT-23-3); Alternate Manufacturer: Texas Instruments; SizeAreaWB_mm2: 14.0; U/M: EA; SizeZ_mm: 1.12; SizeX_mm: 2.5; SizeY_mm: 3.0; SizeArea_mm2: 7.5; CompType: IC
U4 U5 = CMP-0074894-1: 100-mA, 30-V, Fixed-Output, Linear-Voltage Regulator, DBZ0003A (SOT-23-3); Alternate PartNumber: TLV76015DBZT; Alternate Manufacturer: Texas Instruments; SizeAreaWB_mm2: 14.0; SizeZ_mm: 1.12; SizeX_mm: 2.5; SizeY_mm: 3.0; SizeArea_mm2: 7.5; CompType: IC; AEC Qualified: N; AEC Category: Q200
XF1 = CMP-0003627-1: Fuse Holder, TR5, TH; Manufacturer: Littelfuse

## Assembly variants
001: not fitted C6 C9 C10 R4 R6 R7 R10 R11 R12 R13 R14 R15 R16 R17 R18 R19 RT1 TP5 U2 U3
